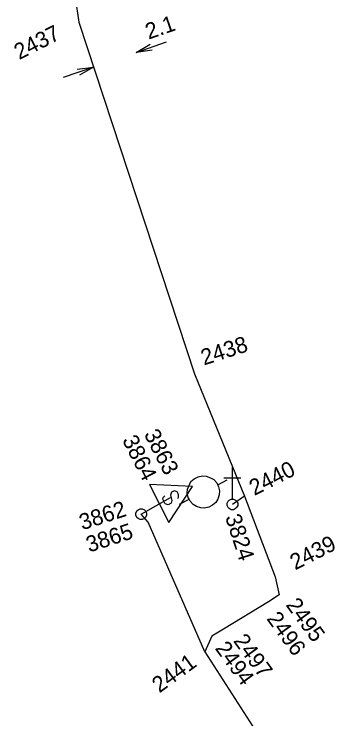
# Model space of a CAD drawing. Extents: x -535557 to -534097, y -1142175 to -1136716.
# Drawn here: x -534929.06 to -534913.65, y -1139115.08 to -1139082.03 of the extents above; entities that cross this region are included whole.
import ezdxf

# ---------------------------------------------------------------- set-up
doc = ezdxf.new("R2010")
doc.units = 0
doc.layers.add('Default', color=7, linetype='Continuous')
doc.layers.add('SS_SZDC', color=7, linetype='Continuous')

# ---------------------------------------------------------------- blocks, each defined once
blk = doc.blocks.new('POINT_DISPLAY')
at = {"layer": 'Default'}
blk.add_line((0, 0), (0, 0), dxfattribs=at)

msp = doc.modelspace()

# ---------------------------------------------------------------- linework, layer by layer
at = {"layer": 'SS_SZDC'}
for p, q in [((-534926.329, -1139080.219), (-534926.029, -1139082.409)), ((-534926.029, -1139082.409), (-534920.6, -1139098.899)), ((-534923.341, -1139083.821), (-534921.923, -1139083.333)), ((-534923.341, -1139083.821), (-534922.681, -1139083.435)), ((-534922.583, -1139083.719), (-534923.341, -1139083.821)), ((-534925.339, -1139084.508), (-534926.757, -1139084.995)), ((-534926.097, -1139084.61), (-534925.339, -1139084.508)), ((-534925.339, -1139084.508), (-534925.999, -1139084.893)), ((-534920.6, -1139098.899), (-534918.26, -1139104.639)), ((-534918.829, -1139104.77), (-534918.829, -1139103.27)), ((-534920.615, -1139103.819), (-534920.437, -1139103.728)), ((-534920.437, -1139103.728), (-534920.236, -1139103.682)), ((-534920.236, -1139103.682), (-534920.057, -1139103.703)), ((-534920.057, -1139103.703), (-534919.855, -1139103.769)), ((-534919.855, -1139103.769), (-534919.698, -1139103.857)), ((-534919.229, -1139103.77), (-534918.429, -1139103.77)), ((-534922.718, -1139104.081), (-534921.81, -1139105.863)), ((-534920.705, -1139104.177), (-534922.718, -1139104.081)), ((-534920.925, -1139104.313), (-534920.771, -1139103.955)), ((-534920.771, -1139103.955), (-534920.615, -1139103.819)), ((-534919.698, -1139103.857), (-534919.563, -1139104.012)), ((-534919.563, -1139104.012), (-534919.472, -1139104.191)), ((-534919.517, -1139104.102), (-534919.072, -1139103.875)), ((-534921.81, -1139105.863), (-534920.705, -1139104.177)), ((-534921.687, -1139104.453), (-534921.73, -1139104.588)), ((-534921.553, -1139104.385), (-534921.687, -1139104.453)), ((-534921.418, -1139104.429), (-534921.553, -1139104.385)), ((-534921.35, -1139104.562), (-534921.418, -1139104.429)), ((-534920.946, -1139104.493), (-534920.925, -1139104.313)), ((-534919.472, -1139104.191), (-534919.426, -1139104.392)), ((-534919.426, -1139104.392), (-534919.447, -1139104.571)), ((-534923.1, -1139105.479), (-534921.729, -1139104.7)), ((-534922.087, -1139104.769), (-534922.065, -1139104.702)), ((-534921.973, -1139104.992), (-534922.087, -1139104.769)), ((-534922.065, -1139104.702), (-534921.998, -1139104.612)), ((-534921.73, -1139104.588), (-534921.661, -1139104.833)), ((-534921.371, -1139104.742), (-534921.35, -1139104.674)), ((-534921.35, -1139104.674), (-534921.35, -1139104.562)), ((-534921.3, -1139105.01), (-534920.854, -1139104.783)), ((-534920.899, -1139104.693), (-534920.946, -1139104.493)), ((-534920.854, -1139104.783), (-534920.899, -1139104.693)), ((-534920.809, -1139104.872), (-534920.854, -1139104.783)), ((-534919.512, -1139104.772), (-534919.601, -1139104.93)), ((-534919.447, -1139104.571), (-534919.512, -1139104.772)), ((-534918.979, -1139104.82), (-534918.879, -1139104.77)), ((-534918.879, -1139104.77), (-534918.779, -1139104.77)), ((-534918.26, -1139104.639), (-534918.829, -1139105.02)), ((-534918.779, -1139104.77), (-534918.679, -1139104.82)), ((-534918.26, -1139104.639), (-534916.829, -1139108.42)), ((-534921.839, -1139105.036), (-534921.973, -1139104.992)), ((-534921.705, -1139104.968), (-534921.839, -1139105.036)), ((-534921.661, -1139104.833), (-534921.705, -1139104.968)), ((-534920.673, -1139105.027), (-534920.809, -1139104.872)), ((-534920.516, -1139105.115), (-534920.673, -1139105.027)), ((-534920.314, -1139105.181), (-534920.516, -1139105.115)), ((-534919.756, -1139105.065), (-534919.934, -1139105.156)), ((-534919.601, -1139104.93), (-534919.756, -1139105.065)), ((-534919.079, -1139104.97), (-534919.029, -1139104.87)), ((-534919.079, -1139105.07), (-534919.079, -1139104.97)), ((-534919.029, -1139105.17), (-534919.079, -1139105.07)), ((-534919.029, -1139104.87), (-534918.979, -1139104.82)), ((-534918.679, -1139104.82), (-534918.629, -1139104.87)), ((-534918.629, -1139104.87), (-534918.579, -1139104.97)), ((-534918.579, -1139105.07), (-534918.629, -1139105.17)), ((-534918.579, -1139104.97), (-534918.579, -1139105.07)), ((-534923.35, -1139105.429), (-534923.3, -1139105.329)), ((-534923.35, -1139105.529), (-534923.35, -1139105.429)), ((-534923.3, -1139105.329), (-534923.25, -1139105.279)), ((-534923.25, -1139105.279), (-534923.15, -1139105.229)), ((-534923.15, -1139105.229), (-534923.05, -1139105.229)), ((-534923.05, -1139105.229), (-534922.95, -1139105.279)), ((-534922.95, -1139105.279), (-534922.9, -1139105.329)), ((-534922.9, -1139105.329), (-534922.85, -1139105.429)), ((-534922.85, -1139105.429), (-534922.85, -1139105.529)), ((-534920.135, -1139105.202), (-534920.314, -1139105.181)), ((-534919.934, -1139105.156), (-534920.135, -1139105.202)), ((-534918.979, -1139105.22), (-534919.029, -1139105.17)), ((-534918.879, -1139105.27), (-534918.979, -1139105.22)), ((-534918.779, -1139105.27), (-534918.879, -1139105.27)), ((-534918.679, -1139105.22), (-534918.779, -1139105.27)), ((-534918.629, -1139105.17), (-534918.679, -1139105.22)), ((-534923.3, -1139105.629), (-534923.35, -1139105.529)), ((-534923.25, -1139105.679), (-534923.3, -1139105.629)), ((-534923.15, -1139105.729), (-534923.25, -1139105.679)), ((-534923.05, -1139105.729), (-534923.15, -1139105.729)), ((-534922.77, -1139105.86), (-534923.1, -1139105.479)), ((-534922.95, -1139105.679), (-534923.05, -1139105.729)), ((-534922.9, -1139105.629), (-534922.95, -1139105.679)), ((-534922.85, -1139105.529), (-534922.9, -1139105.629)), ((-534920.119, -1139111.93), (-534922.77, -1139105.86)), ((-534916.829, -1139108.42), (-534916.64, -1139109.26)), ((-534916.64, -1139109.26), (-534917.14, -1139109.59)), ((-534917.14, -1139109.59), (-534919.25, -1139110.87)), ((-534919.25, -1139110.87), (-534919.789, -1139111.2)), ((-534919.789, -1139111.2), (-534920.119, -1139111.93)), ((-534920.119, -1139111.93), (-534913.649, -1139121.989))]:
    msp.add_line(p, q, dxfattribs=at)

# ---------------------------------------------------------------- block references
for p in [(-534926.029, -1139082.409), (-534920.6, -1139098.899), (-534921.729, -1139104.7), (-534918.26, -1139104.639), (-534921.3, -1139105.01), (-534918.829, -1139105.02), (-534918.829, -1139105.02), (-534923.1, -1139105.479), (-534923.1, -1139105.479), (-534922.77, -1139105.86), (-534916.829, -1139108.42), (-534916.64, -1139109.26), (-534917.14, -1139109.59), (-534919.25, -1139110.87), (-534919.789, -1139111.2), (-534920.119, -1139111.93)]:
    msp.add_blockref('POINT_DISPLAY', p, dxfattribs=at)

# ---------------------------------------------------------------- texts
for s, rotation, p in [('2.1', 18.9711, (-534922.754, -1139083.223)), ('2437', 27, (-534928.818, -1139084.185)), ('2438', 18, (-534920.162, -1139098.509)), ('3863', 297, (-534922.988, -1139101.725)), ('3864', 297, (-534924.01, -1139102.003)), ('2440', 27, (-534917.799, -1139104.628)), ('3862', 18, (-534925.862, -1139106.238)), ('3824', 288, (-534919.176, -1139105.611)), ('3865', 18, (-534925.542, -1139107.283)), ('2439', 27, (-534915.886, -1139108.119)), ('2495', 306, (-534916.349, -1139109.742)), ('2496', 306, (-534917.251, -1139110.386)), ('2497', 306, (-534918.81, -1139111.428)), ('2494', 306, (-534919.669, -1139111.776)), ('2441', 36, (-534922.249, -1139113.889))]:
    msp.add_text(s, height=0.75, rotation=rotation, dxfattribs=at).set_placement(p)

doc.saveas('drawing.dxf')
